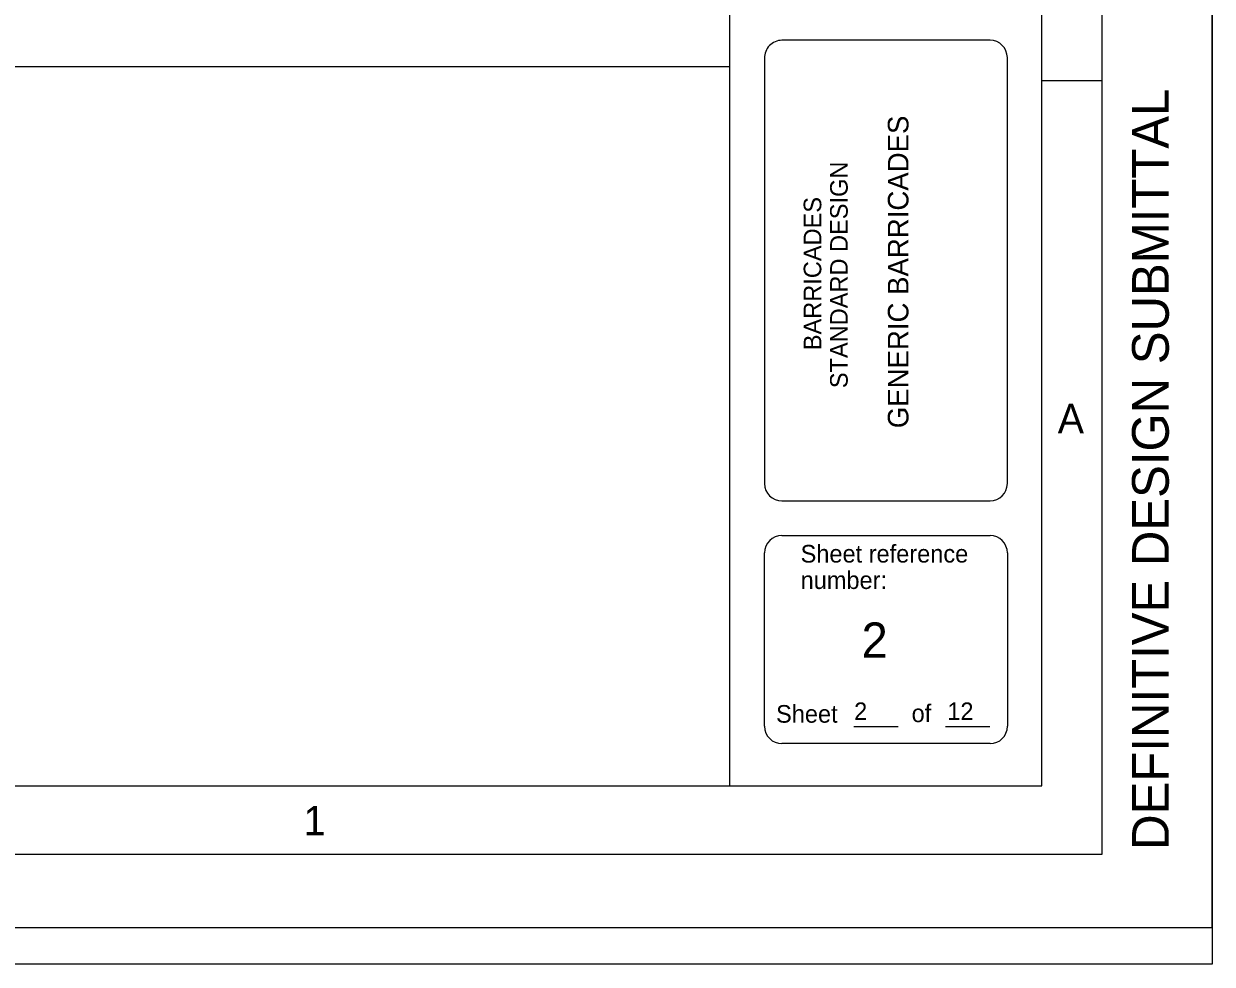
# Model space of a CAD drawing. Extents: x -0.04 to 2.79, y -0.02 to 1.81.
# Drawn here: x 2.117 to 2.792, y -0.021 to 0.513 of the extents above; entities that cross this region are included whole.
import ezdxf

# ---------------------------------------------------------------- set-up
doc = ezdxf.new("R2010")
doc.units = 0
for name, color, linetype in [('G-ANNO-INST', 7, 'Continuous'), ('G-ANNO-NPLT', 7, 'Continuous'), ('G-ANNO-PLOT', 7, 'Continuous'), ('G-ANNO-TTLB', 7, 'Continuous')]:
    doc.layers.add(name, color=color, linetype=linetype)

msp = doc.modelspace()

# ---------------------------------------------------------------- linework, layer by layer
msp.add_line((0.11656, 0.48847), (2.51784, 0.48847))
at = {"layer": 'G-ANNO-NPLT'}
msp.add_lwpolyline([(-0.04167, 1.8125), (2.79167, 1.8125), (2.79167, -0.02083), (-0.04167, -0.02083)], close=True, dxfattribs=at)
at = {"layer": 'G-ANNO-PLOT'}
for p, q in [((2.79167, 1.8125), (2.79167, -0.02083)), ((2.79167, -0.02083), (-0.04167, -0.02083))]:
    msp.add_line(p, q, dxfattribs=at)
msp.add_lwpolyline([(0, 0), (2.79167, 0), (2.79167, 1.79167), (0, 1.79167)], close=True, dxfattribs=at)
at = {"layer": 'G-ANNO-TTLB'}
for p, q in [((2.51784, 0.08028), (2.51784, 1.71305)), ((2.69501, 0.48055), (2.72917, 0.48055)), ((2.58829, 0.11411), (2.61339, 0.11411)), ((2.64031, 0.11411), (2.6654, 0.11411))]:
    msp.add_line(p, q, dxfattribs=at)
for points in [[(0.08333, 0.04167), (2.72917, 0.04167), (2.72917, 1.75), (0.2515, 1.75)], [(0.11656, 0.08028), (2.69501, 0.08028), (2.69501, 1.71305), (0.11656, 1.71305)], [(2.66552, 0.50331), (2.54741, 0.50331)], [(2.53757, 0.49304), (2.53757, 0.25184)], [(2.67536, 0.25184), (2.67536, 0.49348)], [(2.54741, 0.242), (2.66552, 0.242)], [(2.54741, 0.22241), (2.66552, 0.22241)], [(2.53757, 0.11415), (2.53757, 0.21257)], [(2.67536, 0.21257), (2.67536, 0.11415)], [(2.66552, 0.1043), (2.54741, 0.1043)]]:
    msp.add_lwpolyline(points, dxfattribs=at)
for centre, major_axis, start_param, end_param in [((2.5474, 0.49348), (-0.00984, 0), 4.712389, 6.327939), ((2.66552, 0.49348), (0.00984, 0), 0, 1.570796), ((2.5474, 0.25182), (-0.00984, 0), 0, 1.570796), ((2.66552, 0.25182), (0.00984, 0), 4.712389, 6.283185), ((2.54741, 0.21255), (-0.00984, 0), 4.712389, 6.283185), ((2.66553, 0.21255), (0.00984, 0), 0, 1.570796), ((2.54741, 0.11413), (-0.00984, 0), 0, 1.570796), ((2.66553, 0.11413), (0.00984, 0), 4.712389, 6.283185)]:
    msp.add_ellipse(centre, major_axis=major_axis, ratio=0.999936, start_param=start_param, end_param=end_param, dxfattribs=at)

# ---------------------------------------------------------------- texts
at = {"layer": 'G-ANNO-INST'}
msp.add_text('2', height=0.02, dxfattribs=at).set_placement((2.59261, 0.15306))
at = {"layer": 'G-ANNO-TTLB'}
for s, height, p in [('DEFINITIVE DESIGN SUBMITTAL', 0.0208333, (2.767, 0.04403)), ('GENERIC BARRICADES', 0.0117, (2.61923, 0.28325)), ('STANDARD DESIGN', 0.01, (2.58475, 0.30597)), ('BARRICADES', 0.01, (2.56975, 0.3275))]:
    msp.add_text(s, height=height, rotation=90, dxfattribs=at).set_placement(p)
for s, height, p in [('A', 0.01667, (2.70398, 0.28042)), ('Sheet reference', 0.01, (2.55801, 0.20704)), ('number:', 0.01, (2.55801, 0.19204)), ('Sheet', 0.01, (2.54408, 0.11618)), ('2', 0.01, (2.58838, 0.11767)), ('of', 0.01, (2.62101, 0.11652)), ('12', 0.01, (2.64127, 0.11767)), ('1', 0.01667, (2.27587, 0.05228))]:
    msp.add_text(s, height=height, dxfattribs=at).set_placement(p)

doc.saveas('drawing.dxf')
